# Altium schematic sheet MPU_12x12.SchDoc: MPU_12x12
size A3; DocumentNumber: MB1272; Revision: A-01; SheetNumber: 3; SheetTotal: 15; Project: STM32MP15-DISCO PI
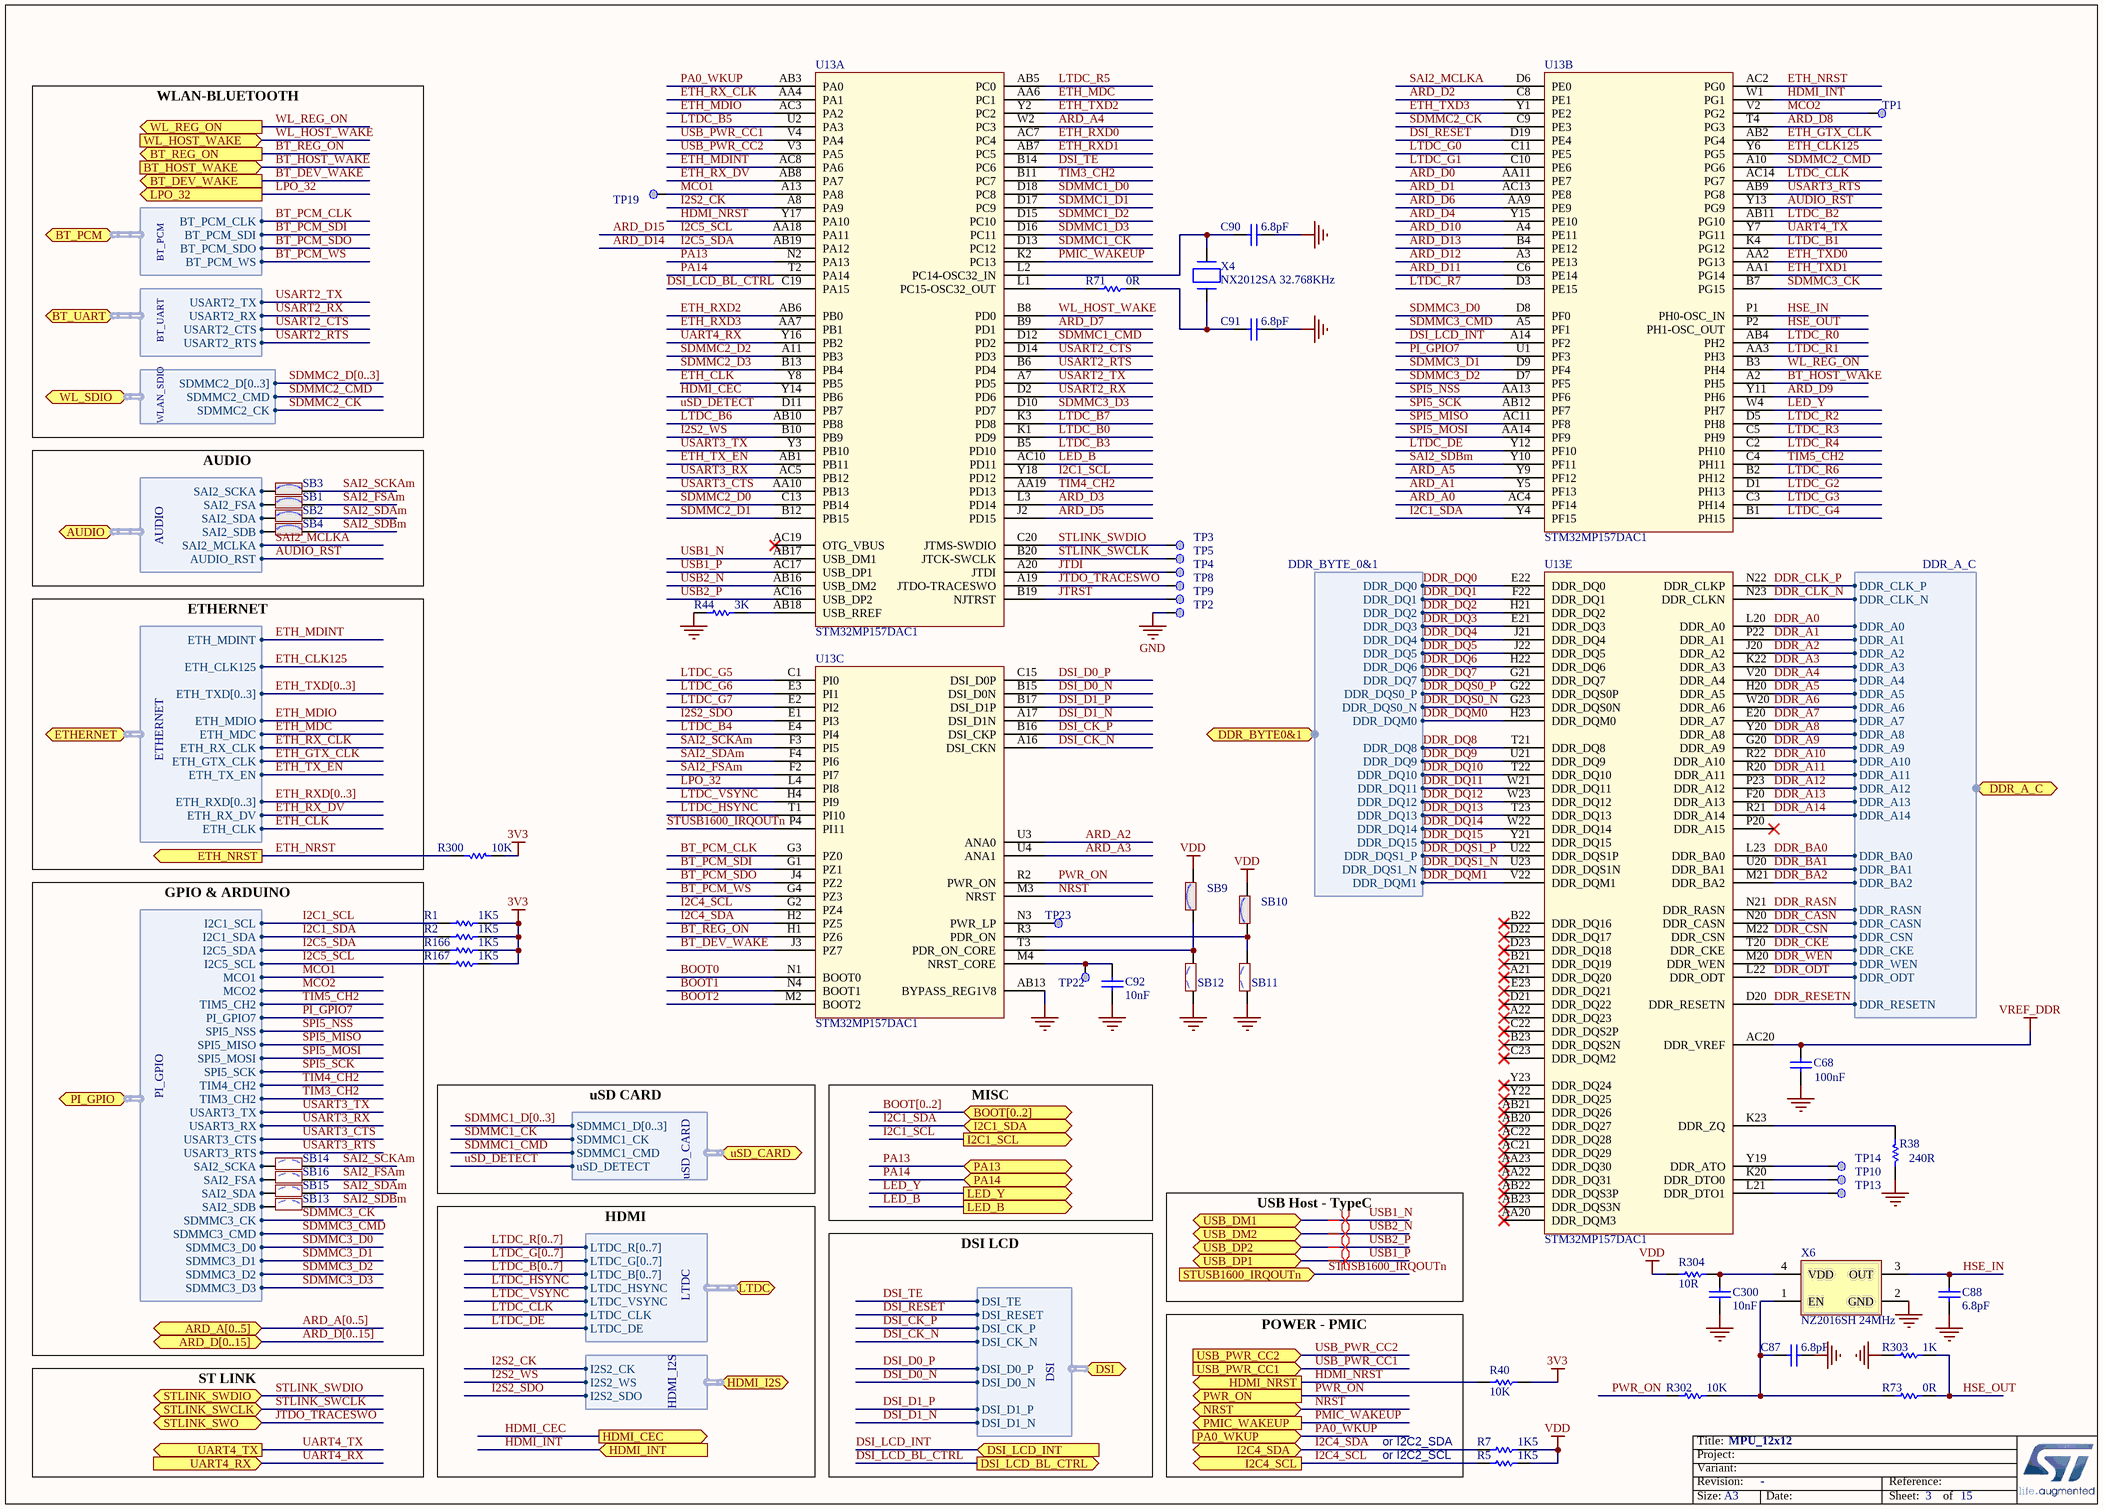
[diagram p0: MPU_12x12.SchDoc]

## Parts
C68  value 100nF  [C0402]
C87  value 6.8pF  [C0402]  (hidden comment: Capacitor)
C88  value 6.8pF  [C0402]  (hidden comment: Capacitor)
C90  value 6.8pF  [C0402]  (hidden comment: Capacitor)
C91  value 6.8pF  [C0402]  (hidden comment: Capacitor)
C92  value 10nF  [C0402]  (hidden comment: Capacitor)
C300  value 10nF  [C0402]  (hidden comment: Capacitor)
R1  value 1K5  [R0402]
R2  value 1K5  [R0402]
R5  value 1K5  [R0402]
R7  value 1K5  [R0402]
R38  value 240R  [R0402]
R40  value 10K  [R0402]  (hidden comment: Resistor)
R44  value 3K  [R0402]
R71  value 0R  [R0402]
R73  value 0R  [R0402]
R166  value 1K5  [R0402]
R167  value 1K5  [R0402]
R300  value 10K  [R0402]  (hidden comment: Resistor)
R302  value 10K  [R0402]  (hidden comment: Resistor)
R303  value 1K  [R0402]
R304  value 10R  [R0402]  (hidden comment: Resistor)
SB1  (no value)  [SOLDER-BRIDGE_R0603-0R]
SB2  (no value)  [SOLDER-BRIDGE_R0603-0R]
SB3  (no value)  [SOLDER-BRIDGE_R0603-0R]
SB4  (no value)  [SOLDER-BRIDGE_R0603-0R]
SB9  (no value)  [SOLDER-BRIDGE_R0603-0R]
SB10  (no value)  [SOLDER-BRIDGE_R0603-0R]
SB11  (no value)  [SOLDER-BRIDGE_R0603-0R]
SB12  (no value)  [SOLDER-BRIDGE_R0603-0R]
SB13  (no value)  [SOLDER-BRIDGE_R0603-0R]
SB14  (no value)  [SOLDER-BRIDGE_R0603-0R]
SB15  (no value)  [SOLDER-BRIDGE_R0603-0R]
SB16  (no value)  [SOLDER-BRIDGE_R0603-0R]
TP1  Test Point  [TP_SMD_1MM]  (value not drawn)  (no BOM)
TP2  Test Point  [TP_SMD_1MM]  (value not drawn)  (no BOM)
TP3  Test Point  [TP_SMD_1MM]  (value not drawn)  (no BOM)
TP4  Test Point  [TP_SMD_1MM]  (value not drawn)  (no BOM)
TP5  Test Point  [TP_SMD_1MM]  (value not drawn)  (no BOM)
TP8  Test Point  [TP_SMD_1MM]  (value not drawn)  (no BOM)
TP9  Test Point  [TP_SMD_1MM]  (value not drawn)  (no BOM)
TP10  (no value)  [TP_SMD_0-6MM]
TP13  (no value)  [TP_SMD_0-6MM]
TP14  (no value)  [TP_SMD_0-6MM]
TP19  Test Point  [TP_SMD_1MM]  (value not drawn)  (no BOM)
TP22  Test Point  [TP_SMD_1MM]  (value not drawn)  (no BOM)
TP23  Test Point  [TP_SMD_1MM]  (value not drawn)  (no BOM)
U13  value STM32MP157DAC1  [ICC_TFBGA361_12X12_STM32MP157CAC3_P050-065]  (parts A,B,C,E of 5)
X4  value NX2012SA 32.768KHz  [CRY_NX2012SA_2P]  (hidden comment: XTAL_2_PINS)
X6  value NZ2016SH 24MHz  [CRY_NZ2016SH_4P]  (hidden comment: OSCILLATOR_4_PINS)

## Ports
ARD_A[0..5], ARD_D[0..15], AUDIO (harness AUDIO), BOOT[0..2], BT_DEV_WAKE (out), BT_HOST_WAKE (in), BT_PCM (harness BT_PCM), BT_REG_ON (out), BT_UART (harness BT_UART), DDR_A_C (harness DDR_A_C), DDR_BYTE0&1 (harness DDR_BYTE_0&1), DSI (harness DSI), DSI_LCD_BL_CTRL (out), DSI_LCD_INT (in), ETH_NRST (out), ETHERNET (harness ETHERNET), HDMI_CEC (out), HDMI_I2S (harness HDMI_I2S), HDMI_INT (in), HDMI_NRST (out), I2C1_SCL (out), I2C1_SDA (bidir), I2C4_SCL (out), I2C4_SDA (bidir), LED_B (out), LED_Y (out), LPO_32 (out), LTDC (harness LTDC), NRST (bidir), PA0_WKUP (in), PA13, PA14, PI_GPIO (harness PI_GPIO), PMIC_WAKEUP (out), PWR_ON (out), STLINK_SWCLK, STLINK_SWDIO, STLINK_SWO, STUSB1600_IRQOUTn (in), UART4_RX (in), UART4_TX (out), USB_DM1 (bidir), USB_DM2 (bidir), USB_DP1 (bidir), USB_DP2 (bidir), USB_PWR_CC1 (in), USB_PWR_CC2 (in), uSD_CARD (harness uSD_CARD), WL_HOST_WAKE (in), WL_REG_ON (out), WL_SDIO (harness WLAN_SDIO)

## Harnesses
DDR_BYTE_0&1: DDR_DQ0, DDR_DQ1, DDR_DQ2, DDR_DQ3, DDR_DQ4, DDR_DQ5, DDR_DQ6, DDR_DQ7, DDR_DQS0_P, DDR_DQS0_N, DDR_DQM0, DDR_DQ8, DDR_DQ9, DDR_DQ10, DDR_DQ11, DDR_DQ12, DDR_DQ13, DDR_DQ14, DDR_DQ15, DDR_DQS1_P, DDR_DQS1_N, DDR_DQM1
DDR_A_C: DDR_CLK_P, DDR_CLK_N, DDR_A0, DDR_A1, DDR_A2, DDR_A3, DDR_A4, DDR_A5, DDR_A6, DDR_A7, DDR_A8, DDR_A9, DDR_A10, DDR_A11, DDR_A12, DDR_A13, DDR_A14, DDR_BA0, DDR_BA1, DDR_BA2, DDR_RASN, DDR_CASN, DDR_CSN, DDR_CKE, DDR_WEN, DDR_ODT, DDR_RESETN
PI_GPIO: I2C1_SCL, I2C1_SDA, I2C5_SDA, MCO1, MCO2, TIM5_CH2, PI_GPIO7, SPI5_NSS, SPI5_MISO, SPI5_MOSI, SPI5_SCK, TIM4_CH2, TIM3_CH2, USART3_TX, USART3_RX, USART3_CTS, USART3_RTS, SDMMC3_CK, SDMMC3_CMD, SDMMC3_D0, SDMMC3_D1, SDMMC3_D2, SDMMC3_D3, I2C5_SCL, SAI2_SCKA, SAI2_FSA, SAI2_SDA, SAI2_SDB
ETHERNET: ETH_MDINT, ETH_CLK125, ETH_TXD[0..3], ETH_MDIO, ETH_MDC, ETH_RX_CLK, ETH_GTX_CLK, ETH_TX_EN, ETH_RXD[0..3], ETH_RX_DV, ETH_CLK
AUDIO: SAI2_SCKA, SAI2_FSA, SAI2_SDA, SAI2_SDB, SAI2_MCLKA, AUDIO_RST
LTDC: LTDC_R[0..7], LTDC_G[0..7], LTDC_B[0..7], LTDC_HSYNC, LTDC_VSYNC, LTDC_CLK, LTDC_DE
uSD_CARD: SDMMC1_D[0..3], SDMMC1_CK, SDMMC1_CMD, uSD_DETECT
BT_PCM: BT_PCM_CLK, BT_PCM_SDI, BT_PCM_SDO, BT_PCM_WS
BT_UART: USART2_TX, USART2_RX, USART2_CTS, USART2_RTS
WLAN_SDIO: SDMMC2_D[0..3], SDMMC2_CMD, SDMMC2_CK
HDMI_I2S: I2S2_CK, I2S2_SDO, I2S2_WS
DSI: DSI_CK_P, DSI_CK_N, DSI_D0_P, DSI_D0_N, DSI_D1_P, DSI_D1_N, DSI_TE, DSI_RESET

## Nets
3V3: R1.1 R2.1 R40.1 R166.1 R167.1 R300.1
GND: C68.1 C87.2 C88.1 C90.2 C91.2 C92.1 C300.1 R38.2 R44.1 R303.2 SB11.1 SB12.1 TP2.1 U13.AB13(BYPASS_REG1V8) X6.2(GND)
VDD: R5.1 R7.1 R304.1 SB9.2 SB10.2
VREF_DDR: C68.2 U13.AC20(DDR_VREF)
ARD_A0: U13.AC4(PF14)
ARD_A1: U13.Y5(PF13)
ARD_A2: U13.U3(ANA0)
ARD_A3: U13.U4(ANA1)
ARD_A4: U13.W2(PC3)
ARD_A5: U13.Y9(PF12)
ARD_D0: U13.AA11(PE7)
ARD_D1: U13.AC13(PE8)
ARD_D2: U13.C8(PE1)
ARD_D3: U13.L3(PD14)
ARD_D4: U13.Y15(PE10)
ARD_D5: U13.J2(PD15)
ARD_D6: U13.AA9(PE9)
ARD_D7: U13.B9(PD1)
ARD_D8: U13.T4(PG3)
ARD_D9: U13.Y11(PH6)
ARD_D10: U13.A4(PE11)
ARD_D11: U13.C6(PE14)
ARD_D12: U13.A3(PE13)
ARD_D13: U13.B4(PE12)
ARD_D14: R166.2 U13.AB19(PA12) ; port PI_GPIO.I2C5_SDA  [also labelled I2C5_SDA]
ARD_D15: R167.2 U13.AA18(PA11) ; port PI_GPIO.I2C5_SCL  [also labelled I2C5_SCL]
AUDIO_RST: U13.Y13(PG9) ; port AUDIO.AUDIO_RST
BOOT0: U13.N1(BOOT0)
BOOT1: U13.N4(BOOT1)
BOOT2: U13.M2(BOOT2)
BT_DEV_WAKE: U13.J3(PZ7) ; port BT_DEV_WAKE
BT_HOST_WAKE: U13.A2(PH5) ; port BT_HOST_WAKE
BT_PCM_CLK: U13.G3(PZ0) ; port BT_PCM.BT_PCM_CLK
BT_PCM_SDI: U13.G1(PZ1) ; port BT_PCM.BT_PCM_SDI
BT_PCM_SDO: U13.J4(PZ2) ; port BT_PCM.BT_PCM_SDO
BT_PCM_WS: U13.G4(PZ3) ; port BT_PCM.BT_PCM_WS
BT_REG_ON: U13.H1(PZ6) ; port BT_REG_ON
DDR_A0: U13.L20(DDR_A0) ; port DDR_A_C.DDR_A0
DDR_A1: U13.P22(DDR_A1) ; port DDR_A_C.DDR_A1
DDR_A2: U13.J20(DDR_A2) ; port DDR_A_C.DDR_A2
DDR_A3: U13.K22(DDR_A3) ; port DDR_A_C.DDR_A3
DDR_A4: U13.V20(DDR_A4) ; port DDR_A_C.DDR_A4
DDR_A5: U13.H20(DDR_A5) ; port DDR_A_C.DDR_A5
DDR_A6: U13.W20(DDR_A6) ; port DDR_A_C.DDR_A6
DDR_A7: U13.E20(DDR_A7) ; port DDR_A_C.DDR_A7
DDR_A8: U13.Y20(DDR_A8) ; port DDR_A_C.DDR_A8
DDR_A9: U13.G20(DDR_A9) ; port DDR_A_C.DDR_A9
DDR_A10: U13.R22(DDR_A10) ; port DDR_A_C.DDR_A10
DDR_A11: U13.R20(DDR_A11) ; port DDR_A_C.DDR_A11
DDR_A12: U13.P23(DDR_A12) ; port DDR_A_C.DDR_A12
DDR_A13: U13.F20(DDR_A13) ; port DDR_A_C.DDR_A13
DDR_A14: U13.R21(DDR_A14) ; port DDR_A_C.DDR_A14
DDR_BA0: U13.L23(DDR_BA0) ; port DDR_A_C.DDR_BA0
DDR_BA1: U13.U20(DDR_BA1) ; port DDR_A_C.DDR_BA1
DDR_BA2: U13.M21(DDR_BA2) ; port DDR_A_C.DDR_BA2
DDR_CASN: U13.N20(DDR_CASN) ; port DDR_A_C.DDR_CASN
DDR_CKE: U13.T20(DDR_CKE) ; port DDR_A_C.DDR_CKE
DDR_CLK_N: U13.N23(DDR_CLKN) ; port DDR_A_C.DDR_CLK_N
DDR_CLK_P: U13.N22(DDR_CLKP) ; port DDR_A_C.DDR_CLK_P
DDR_CSN: U13.M22(DDR_CSN) ; port DDR_A_C.DDR_CSN
DDR_DQ0: U13.E22(DDR_DQ0) ; port DDR_BYTE0&1.DDR_DQ0
DDR_DQ1: U13.F22(DDR_DQ1) ; port DDR_BYTE0&1.DDR_DQ1
DDR_DQ2: U13.H21(DDR_DQ2) ; port DDR_BYTE0&1.DDR_DQ2
DDR_DQ3: U13.E21(DDR_DQ3) ; port DDR_BYTE0&1.DDR_DQ3
DDR_DQ4: U13.J21(DDR_DQ4) ; port DDR_BYTE0&1.DDR_DQ4
DDR_DQ5: U13.J22(DDR_DQ5) ; port DDR_BYTE0&1.DDR_DQ5
DDR_DQ6: U13.H22(DDR_DQ6) ; port DDR_BYTE0&1.DDR_DQ6
DDR_DQ7: U13.G21(DDR_DQ7) ; port DDR_BYTE0&1.DDR_DQ7
DDR_DQ8: U13.T21(DDR_DQ8) ; port DDR_BYTE0&1.DDR_DQ8
DDR_DQ9: U13.U21(DDR_DQ9) ; port DDR_BYTE0&1.DDR_DQ9
DDR_DQ10: U13.T22(DDR_DQ10) ; port DDR_BYTE0&1.DDR_DQ10
DDR_DQ11: U13.W21(DDR_DQ11) ; port DDR_BYTE0&1.DDR_DQ11
DDR_DQ12: U13.W23(DDR_DQ12) ; port DDR_BYTE0&1.DDR_DQ12
DDR_DQ13: U13.T23(DDR_DQ13) ; port DDR_BYTE0&1.DDR_DQ13
DDR_DQ14: U13.W22(DDR_DQ14) ; port DDR_BYTE0&1.DDR_DQ14
DDR_DQ15: U13.Y21(DDR_DQ15) ; port DDR_BYTE0&1.DDR_DQ15
DDR_DQM0: U13.H23(DDR_DQM0) ; port DDR_BYTE0&1.DDR_DQM0
DDR_DQM1: U13.V22(DDR_DQM1) ; port DDR_BYTE0&1.DDR_DQM1
DDR_DQS0_N: U13.G23(DDR_DQS0N) ; port DDR_BYTE0&1.DDR_DQS0_N
DDR_DQS0_P: U13.G22(DDR_DQS0P) ; port DDR_BYTE0&1.DDR_DQS0_P
DDR_DQS1_N: U13.U23(DDR_DQS1N) ; port DDR_BYTE0&1.DDR_DQS1_N
DDR_DQS1_P: U13.U22(DDR_DQS1P) ; port DDR_BYTE0&1.DDR_DQS1_P
DDR_ODT: U13.L22(DDR_ODT) ; port DDR_A_C.DDR_ODT
DDR_RASN: U13.N21(DDR_RASN) ; port DDR_A_C.DDR_RASN
DDR_RESETN: U13.D20(DDR_RESETN) ; port DDR_A_C.DDR_RESETN
DDR_WEN: U13.M20(DDR_WEN) ; port DDR_A_C.DDR_WEN
DSI_CK_N: U13.A16(DSI_CKN) ; port DSI.DSI_CK_N
DSI_CK_P: U13.B16(DSI_CKP) ; port DSI.DSI_CK_P
DSI_D0_N: U13.B15(DSI_D0N) ; port DSI.DSI_D0_N
DSI_D0_P: U13.C15(DSI_D0P) ; port DSI.DSI_D0_P
DSI_D1_N: U13.A17(DSI_D1N) ; port DSI.DSI_D1_N
DSI_D1_P: U13.B17(DSI_D1P) ; port DSI.DSI_D1_P
DSI_LCD_BL_CTRL: U13.C19(PA15) ; port DSI_LCD_BL_CTRL
DSI_LCD_INT: U13.A14(PF2) ; port DSI_LCD_INT
DSI_RESET: U13.D19(PE4) ; port DSI.DSI_RESET
DSI_TE: U13.B14(PC6) ; port DSI.DSI_TE
ETH_CLK: U13.Y8(PB5) ; port ETHERNET.ETH_CLK
ETH_CLK125: U13.Y6(PG5) ; port ETHERNET.ETH_CLK125
ETH_GTX_CLK: U13.AB2(PG4) ; port ETHERNET.ETH_GTX_CLK
ETH_MDC: U13.AA6(PC1) ; port ETHERNET.ETH_MDC
ETH_MDINT: U13.AC8(PA6) ; port ETHERNET.ETH_MDINT
ETH_MDIO: U13.AC3(PA2) ; port ETHERNET.ETH_MDIO
ETH_NRST: R300.2 U13.AC2(PG0) ; port ETH_NRST
ETH_RX_CLK: U13.AA4(PA1) ; port ETHERNET.ETH_RX_CLK
ETH_RX_DV: U13.AB8(PA7) ; port ETHERNET.ETH_RX_DV
ETH_RXD0: U13.AC7(PC4)
ETH_RXD1: U13.AB7(PC5)
ETH_RXD2: U13.AB6(PB0)
ETH_RXD3: U13.AA7(PB1)
ETH_TX_EN: U13.AB1(PB11) ; port ETHERNET.ETH_TX_EN
ETH_TXD0: U13.AA2(PG13)
ETH_TXD1: U13.AA1(PG14)
ETH_TXD2: U13.Y2(PC2)
ETH_TXD3: U13.Y1(PE2)
HDMI_CEC: U13.Y14(PB6) ; port HDMI_CEC
HDMI_INT: U13.W1(PG1) ; port HDMI_INT
HDMI_NRST: R40.2 U13.Y17(PA10) ; port HDMI_NRST
HSE_IN: C88.2 U13.P1(PH0-OSC_IN) X6.3(OUT)
HSE_OUT: R73.2 R303.1 U13.P2(PH1-OSC_OUT)
I2C1_SCL: R1.2 U13.Y18(PD12) ; port I2C1_SCL, port PI_GPIO.I2C1_SCL
I2C1_SDA: R2.2 U13.Y4(PF15) ; port I2C1_SDA, port PI_GPIO.I2C1_SDA
I2C4_SCL: R5.2 U13.G2(PZ4) ; port I2C4_SCL
I2C4_SDA: R7.2 U13.H2(PZ5) ; port I2C4_SDA
I2S2_CK: U13.A8(PA9) ; port HDMI_I2S.I2S2_CK
I2S2_SDO: U13.E1(PI3) ; port HDMI_I2S.I2S2_SDO
I2S2_WS: U13.B10(PB9) ; port HDMI_I2S.I2S2_WS
JTDI: TP4.1 U13.A20(JTDI)
JTDO_TRACESWO: TP8.1 U13.A19(JTDO-TRACESWO) ; port STLINK_SWO
JTRST: TP9.1 U13.B19(NJTRST)
LED_B: U13.AC10(PD11) ; port LED_B
LED_Y: U13.W4(PH7) ; port LED_Y
LPO_32: U13.L4(PI8) ; port LPO_32
LTDC_B0: U13.K1(PD9)
LTDC_B1: U13.K4(PG12)
LTDC_B2: U13.AB11(PG10)
LTDC_B3: U13.B5(PD10)
LTDC_B4: U13.E4(PI4)
LTDC_B5: U13.U2(PA3)
LTDC_B6: U13.AB10(PB8)
LTDC_B7: U13.K3(PD8)
LTDC_CLK: U13.AC14(PG7) ; port LTDC.LTDC_CLK
LTDC_DE: U13.Y12(PF10) ; port LTDC.LTDC_DE
LTDC_G0: U13.C11(PE5)
LTDC_G1: U13.C10(PE6)
LTDC_G2: U13.D1(PH13)
LTDC_G3: U13.C3(PH14)
LTDC_G4: U13.B1(PH15)
LTDC_G5: U13.C1(PI0)
LTDC_G6: U13.E3(PI1)
LTDC_G7: U13.E2(PI2)
LTDC_HSYNC: U13.T1(PI10) ; port LTDC.LTDC_HSYNC
LTDC_R0: U13.AB4(PH2)
LTDC_R1: U13.AA3(PH3)
LTDC_R2: U13.D5(PH8)
LTDC_R3: U13.C5(PH9)
LTDC_R4: U13.C2(PH10)
LTDC_R5: U13.AB5(PC0)
LTDC_R6: U13.B2(PH12)
LTDC_R7: U13.D3(PE15)
LTDC_VSYNC: U13.H4(PI9) ; port LTDC.LTDC_VSYNC
MCO1: TP19.1 U13.A13(PA8) ; port PI_GPIO.MCO1
MCO2: TP1.1 U13.V2(PG2) ; port PI_GPIO.MCO2
NRST: U13.M3(NRST) ; port NRST
PA0_WKUP: U13.AB3(PA0) ; port PA0_WKUP
PA13: U13.N2(PA13) ; port PA13
PA14: U13.T2(PA14) ; port PA14
PI_GPIO7: U13.U1(PF3) ; port PI_GPIO.PI_GPIO7
PMIC_WAKEUP: U13.K2(PC13) ; port PMIC_WAKEUP
PWR_ON: R302.2 U13.R2(PWR_ON) ; port PWR_ON
SAI2_FSAm: SB1.2 SB16.2 U13.F2(PI7)
SAI2_MCLKA: U13.D6(PE0) ; port AUDIO.SAI2_MCLKA
SAI2_SCKAm: SB3.2 SB14.2 U13.F3(PI5)
SAI2_SDAm: SB2.2 SB15.2 U13.F4(PI6)
SAI2_SDBm: SB4.2 SB13.2 U13.Y10(PF11)
SDMMC1_CK: U13.D13(PC12) ; port uSD_CARD.SDMMC1_CK
SDMMC1_CMD: U13.D12(PD2) ; port uSD_CARD.SDMMC1_CMD
SDMMC1_D0: U13.D18(PC8)
SDMMC1_D1: U13.D17(PC9)
SDMMC1_D2: U13.D15(PC10)
SDMMC1_D3: U13.D16(PC11)
SDMMC2_CK: U13.C9(PE3) ; port WL_SDIO.SDMMC2_CK
SDMMC2_CMD: U13.A10(PG6) ; port WL_SDIO.SDMMC2_CMD
SDMMC2_D0: U13.C13(PB14)
SDMMC2_D1: U13.B12(PB15)
SDMMC2_D2: U13.A11(PB3)
SDMMC2_D3: U13.B13(PB4)
SDMMC3_CK: U13.B7(PG15) ; port PI_GPIO.SDMMC3_CK
SDMMC3_CMD: U13.A5(PF1) ; port PI_GPIO.SDMMC3_CMD
SDMMC3_D0: U13.D8(PF0) ; port PI_GPIO.SDMMC3_D0
SDMMC3_D1: U13.D9(PF4) ; port PI_GPIO.SDMMC3_D1
SDMMC3_D2: U13.D7(PF5) ; port PI_GPIO.SDMMC3_D2
SDMMC3_D3: U13.D10(PD7) ; port PI_GPIO.SDMMC3_D3
SPI5_MISO: U13.AC11(PF8) ; port PI_GPIO.SPI5_MISO
SPI5_MOSI: U13.AA14(PF9) ; port PI_GPIO.SPI5_MOSI
SPI5_NSS: U13.AA13(PF6) ; port PI_GPIO.SPI5_NSS
SPI5_SCK: U13.AB12(PF7) ; port PI_GPIO.SPI5_SCK
STLINK_SWCLK: TP5.1 U13.B20(JTCK-SWCLK) ; port STLINK_SWCLK
STLINK_SWDIO: TP3.1 U13.C20(JTMS-SWDIO) ; port STLINK_SWDIO
STUSB1600_IRQOUTn: U13.P4(PI11) ; port STUSB1600_IRQOUTn
TIM3_CH2: U13.B11(PC7) ; port PI_GPIO.TIM3_CH2
TIM4_CH2: U13.AA19(PD13) ; port PI_GPIO.TIM4_CH2
TIM5_CH2: U13.C4(PH11) ; port PI_GPIO.TIM5_CH2
UART4_RX: U13.Y16(PB2) ; port UART4_RX
UART4_TX: U13.Y7(PG11) ; port UART4_TX
USART2_CTS: U13.D14(PD3) ; port BT_UART.USART2_CTS
USART2_RTS: U13.B6(PD4) ; port BT_UART.USART2_RTS
USART2_RX: U13.D2(PD6) ; port BT_UART.USART2_RX
USART2_TX: U13.A7(PD5) ; port BT_UART.USART2_TX
USART3_CTS: U13.AA10(PB13) ; port PI_GPIO.USART3_CTS
USART3_RTS: U13.AB9(PG8) ; port PI_GPIO.USART3_RTS
USART3_RX: U13.AC5(PB12) ; port PI_GPIO.USART3_RX
USART3_TX: U13.Y3(PB10) ; port PI_GPIO.USART3_TX
USB1_N: U13.AB17(USB_DM1) ; port USB_DM1
USB1_P: U13.AC17(USB_DP1) ; port USB_DP1
USB2_N: U13.AB16(USB_DM2) ; port USB_DM2
USB2_P: U13.AC16(USB_DP2) ; port USB_DP2
USB_PWR_CC1: U13.V4(PA4) ; port USB_PWR_CC1
USB_PWR_CC2: U13.V3(PA5) ; port USB_PWR_CC2
uSD_DETECT: U13.D11(PB7) ; port uSD_CARD.uSD_DETECT
WL_HOST_WAKE: U13.B8(PD0) ; port WL_HOST_WAKE
WL_REG_ON: U13.B3(PH4) ; port WL_REG_ON
NetC87_1: C87.1 R73.1 R302.1 X6.1(EN)
NetC90_1: C90.1 U13.L2(PC14-OSC32_IN) X4.2(X2)
NetC91_1: C91.1 R71.2 X4.1(X1)
NetC92_2: C92.2 TP22.1 U13.M4(NRST_CORE)
NetC300_2: C300.2 R304.2 X6.4(VDD)
NetR38_1: R38.1 U13.K23(DDR_ZQ)
NetR44_2: R44.2 U13.AB18(USB_RREF)
NetR71_1: R71.1 U13.L1(PC15-OSC32_OUT)
NetSB1_1: SB1.1 ; port AUDIO.SAI2_FSA
NetSB2_1: SB2.1 ; port AUDIO.SAI2_SDA
NetSB3_1: SB3.1 ; port AUDIO.SAI2_SCKA
NetSB4_1: SB4.1 ; port AUDIO.SAI2_SDB
NetSB9_1: SB9.1 SB12.2 U13.T3(PDR_ON_CORE)
NetSB10_1: SB10.1 SB11.2 U13.R3(PDR_ON)
NetSB13_1: SB13.1 ; port PI_GPIO.SAI2_SDB
NetSB14_1: SB14.1 ; port PI_GPIO.SAI2_SCKA
NetSB15_1: SB15.1 ; port PI_GPIO.SAI2_SDA
NetSB16_1: SB16.1 ; port PI_GPIO.SAI2_FSA
NetTP10_1: TP10.1 U13.K20(DDR_DTO0)
NetTP13_1: TP13.1 U13.L21(DDR_DTO1)
NetTP14_1: TP14.1 U13.Y19(DDR_ATO)
NetTP23_1: TP23.1 U13.N3(PWR_LP)

Not connected (* = marked no-connect by the designer): U13 A21(DDR_DQ20)* A22(DDR_DQ23)* AA20(DDR_DQM3)* AA22(DDR_DQ31)* AA23(DDR_DQ30)* AB20(DDR_DQ27)* AB21(DDR_DQ26)* AB22(DDR_DQS3P)* AB23(DDR_DQS3N)* AC19(OTG_VBUS)* AC21(DDR_DQ29)* AC22(DDR_DQ28)* B21(DDR_DQ19)* B22(DDR_DQ16)* B23(DDR_DQS2N)* C22(DDR_DQS2P)* C23(DDR_DQM2)* D21(DDR_DQ22)* D22(DDR_DQ17)* D23(DDR_DQ18)* E23(DDR_DQ21)* P20(DDR_A15)* Y22(DDR_DQ25)* Y23(DDR_DQ24)*

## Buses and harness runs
bus ARD_A[0..5] = port ARD_A[0..5]
bus ARD_D[0..15] = port ARD_D[0..15]
bus BOOT[0..2] = port BOOT[0..2]
bus ETH_RXD[0..3]
bus ETH_TXD[0..3]
bus LTDC_B[0..7]
bus LTDC_G[0..7]
bus LTDC_R[0..7]
bus SDMMC1_D[0..3]
bus SDMMC2_D[0..3]

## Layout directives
differential pair: USB1_N, USB1_P, USB2_N, USB2_P

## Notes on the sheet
- WLAN-BLUETOOTH
- AUDIO
- ETHERNET
- uSD CARD
- MISC
- USB Host - TypeC
- GPIO & ARDUINO
- or I2C2_SDA
- or I2C2_SCL
- ST LINK
- HDMI
- DSI LCD
- POWER - PMIC

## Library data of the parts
C68 = MCD-00006: Capacitor,100nF,16V,X7R,10%,0402; Manufacturer_Part_Number: CC0402KRX7R7BB104; Manufacturer: YAGEO; Alternate_Manufacturer: MURATA; Alternate_Manufacturer_Part_Number: GCM155R71C104KA55D; Provided_By: SUBCO; Initial_Board_Reference: mb1274
C87 C88 = MCD-00674: Capacitor, MLCC, 6.8pF, 50V, NPO, +-0.25pF, 0402, T=0.5mm; Manufacturer_Part_Number: CC0402CRNPO9BN6R8; Manufacturer: YAGEO; Provided_By: SUBCO; Initial_Board_Reference: MB1319
C90 C91 = MCD-00674: Capacitor, MLCC, 6.8pF, 50V, NPO, +-0.25pF, 0402, T=0.5mm; Manufacturer_Part_Number: CC0402CRNPO9BN6R8; Manufacturer: YAGEO; Provided_By: SUBCO; Initial_Board_Reference: MB1319; Path: ws/MCD_ApplicationBoards/Lists/MCDPARTSdatabase; Item Type: Item
C92 C300 = MCD-00011: Capacitor, MLCC, 10nF, 16V, X7R, 10%, 0402, T=0.5mm; Manufacturer_Part_Number: CC0402KRX7R7BB103; Manufacturer: YAGEO; Provided_By: SUBCO; Initial_Board_Reference: MB1274
R1 R2 R5 R7 R166 R167 = MCD-00068: Resistor,1K5,0402,1%,1/16W; Manufacturer_Part_Number: RC0402FR-071K5L; Manufacturer: YAGEO; Provided_By: SUBCO; Initial_Board_Reference: mb1274
R38 = MCD-00120: Resistor,240R,0402,1%,1/16W; Manufacturer_Part_Number: RC0402FR-07240RL; Manufacturer: YAGEO; Provided_By: SUBCO; Initial_Board_Reference: mb1262
R40 R300 R302 = MCD-00053: Resistor,10K,0402,1%,1/16W; Manufacturer_Part_Number: RC0402FR-0710KL; Manufacturer: YAGEO; Provided_By: SUBCO; Initial_Board_Reference: MB1274
R44 = MCD-00185: Resistor,3K,0402,1%,1/16W; Manufacturer_Part_Number: RC0402FR-073KL; Manufacturer: YAGEO; Provided_By: SUBCO
R71 R73 = MCD-00052: Resistor,0R,0402,5%,1/16W; Manufacturer_Part_Number: RC0402JR-070RL; Manufacturer: YAGEO; Provided_By: SUBCO; Initial_Board_Reference: mb1274
R303 = MCD-00061: Resistor,1K,0402,1%,1/16W; Manufacturer_Part_Number: RC0402FR-071KL; Manufacturer: YAGEO; Provided_By: SUBCO; Initial_Board_Reference: mb1274
R304 = MCD-00358: Resistor,10R,0402,1%,1/16W; Manufacturer_Part_Number: RC0402FR-0710RL; Manufacturer: YAGEO; Provided_By: SUBCO
SB1-SB4 SB9 SB10 = MCD-00071: Solder Bridge ON; Part_Type: Mechanical; Manufacturer: YAGEO; Manufacturer_Part_Number: RC0603JR-070RL; Provided_By: SUBCO; Initial_Board_Reference: mb1274
SB11-SB16 = MCD-00072: Solder Bridge OFF; Part_Type: Mechanical; Manufacturer: YAGEO; Manufacturer_Part_Number: RC0603JR-070RL; Provided_By: SUBCO; Initial_Board_Reference: mb1274
TP1-TP5 TP8 TP9 TP19 TP22 TP23 = MCD-00074: Test Point 1mm; Part_Type: Mechanical; Initial_Board_Reference: MB1274
TP10 TP13 TP14 = MCD-00631: Test Point 0.6mm; Part_Type: Mechanical; Initial_Board_Reference: mb1264
U13 = MCD-02020: MPU TFBGA12x12 without crypto increased frequency; Part_Type: IC; Manufacturer: STMICROELECTRONICS; Provided_By: SUBCO with ST control; ECCN_US: 3A991A2; ECCN_EU: NEC
X4 = MCD-01479: Crystal 32.768kHz, 6pF, -+20PPM, R=80K, SMD; Part_Type: Crystal_Osc; Manufacturer_Part_Number: NX2012SA 32.768KHz EXS00A-MU00527; Manufacturer: NDK; Provided_By: SUBCO; Initial_Board_Reference: MB1373; Path: ws/MCD_ApplicationBoards/Lists/MCDPARTSdatabase; Item Type: Item
X6 = MCD-01627: Oscillator 24Mhz, +-50ppm, Vcc:3.3V typ (1.62V min), square wave: [0.1Vcc;0.9Vcc], Enable pin; Part_Type: Crystal_Osc; Manufacturer_Part_Number: NZ2016SH 24MHz END4869F; Manufacturer: NDK; Provided_By: SUBCO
